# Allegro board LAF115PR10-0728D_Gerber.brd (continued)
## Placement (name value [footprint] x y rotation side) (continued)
EC2901  1000P_0402_50V7K  [C_0402]  31.42 64.37 0 top
EC2902  .1U_0402_16V7K  [C_0402]  220.77 66.04 90 top
EC3001  .1U_0402_16V7K  [C_0402]  85.95 47.96 90 top
EC3002  .1U_0402_16V7K  [C_0402]  50.48 41.56 90 top
EC3003  0.1U_0402_25V6  [C_0402]  28.91 23.76 0 top
ED2901  -  [L03ESDL5V0CC3-2_SOT23-3]  32.58 60.6 0 top
EU2601  -  [L05ESDL5V0NA-4_SLP2510P8-10-9]  19.55 56.9 270 top
EU2602  -  [AZC199-02SPR7G_SOT23-3]  30.43 55.79 90 top
EU2603  -  [L05ESDL5V0NA-4_SLP2510P8-10-9]  19.34 30.9 315 top
EU2604  -  [AZC199-02SPR7G_SOT23-3]  28.99 39.56 270 bottom
EU2701  -  [AZC199-02SPR7G_SOT23-3]  219.81 35.37 0 bottom
EU3101  -  [L05ESDL5V0NA-4_SLP2510P8-10-9]  189.37 36.47 0 top
EU4001  -  [L05ESDL5V0NA-4_SLP2510P8-10-9]  19.95 130.36 270 bottom
EU4002  -  [L05ESDL5V0NA-4_SLP2510P8-10-9]  26.88 123.22 180 bottom
EU4011  -  [L30ESD24VC3-2_SOT23-3]  13.65 131 180 top
EU4012  -  [AZC199-02SPR7G_SOT23-3]  52.1 89.7 90 top
F1  1.5A_24V_SMD1812P150TF-24  [F_SMD1812P150TF-24]  209.38 52.42 90 bottom
F2  1.1A_24V_SMD1812P110TF-24  [F_SMD1812P110TF-24]  215.37 37.63 180 top
F3  0.5A_13.2V_MF-NSMF050-2  [F_MF-NSMF050-2]  48.24 41.06 180 top
FD1  FIDUCAL  [FIDUCIAL_C40M80]  13.81 113.14 0 top
FD2  FIDUCAL  [FIDUCIAL_C40M80]  223.33 26.42 0 top
FD3  FIDUCAL  [FIDUCIAL_C40M80]  53.5 138.49 180 bottom
FD4  FIDUCAL  [FIDUCIAL_C40M80]  225.4 55.81 180 bottom
FI1  1.5A_6V_1206L150PR~D  [F_1206L150PR]  16.59 99.9 90 top
H1  HOLEA  [H_3P0]  6.85 130.5 0 top
H3  HOLEA  [H_5P0]  169.05 109.5 0 top
H4  HOLEA  [H_3P0]  7.9 85.8 0 top
H5  HOLEA  [H_3P0-G]  8 41.2 0 top
H6  HOLEA  [H_3P0-G]  207.45 63.85 0 top
H7  HOLEA  [H_3P0]  141.55 27.1 0 top
H8  HOLEA  [H_3P3-G]  6.9 112.6 0 top
H9  HOLEA  [H_3P5]  142.95 117.18 180 bottom
H10  HOLEA  [H_3P5]  101.31 130.35 180 bottom
H11  HOLEA  [H_3P2]  126.01 153.05 180 bottom
H12  HOLEA  [H_3P2-G]  45.5 129.9 0 top
H13  HOLEA  [H_3P0X4P0]  213.85 65.5 90 top
H14  HOLEA  [H_5P6N]  19.1 111.3 90 top
HCPU1  HOLEA  [H_4P0X3P7]  113.08 100.81 0 top
HCPU2  HOLEA  [H_3P7]  137.38 100.78 0 top
HCPU3  HOLEA  [H_4P0]  113.08 39.78 0 top
HCPU4  HOLEA  [H_3P7X4P0]  137.38 39.81 0 top
JCCG4  CVILU_CH31052VA00-NH  [DC021611210]  42.83 115.5 90 bottom
JCMOS1  SHORT PADS~D  [SHORTPADS]  96.9 77 90 bottom
JDEG1  JXT_FP241AH-010GAAM  [JXT_FP241AH-010GAAM_10P]  45.24 88.83 180 bottom
JDIMM1  DEREN_40-42271-26001RHF  [LOTES_ADDR0206-P001A02_260P]  79.15 109.99 90 bottom
JDIMM2  DEREN_40-42261-26001RHF  [LOTES_ADDR0205-P001A02_260P]  66.45 109.99 270 bottom
JEDP1  ACES_51540-04001-P01  [ACES_51540-04001-P01_40P]  212.37 60.45 270 bottom
JESPI1  JXT_FP241AH-010GAAM  [JXT_FP241AH-010GAAM_10P]  44.69 94.37 90 bottom
JFAN1  ACES_50224-00401-001  [ACES_50224-00401-001_4P]  179.96 68.62 45 bottom
JFP  ACES_51522-00601-001  [ACES_51522-00601-001_6P]  220.02 30.77 180 bottom
JFP1  ACES_51522-00801-001  [ACES_51522-00801-001_8P]  221.02 30.77 180 bottom
JHDD  ACES_50406-02071-001  [ACES_50406-02071-001_20P]  180.7 35.58 0 bottom
JHDD1  ACES_51625-01201-001  [ACES_51625-01201-001_12P]  190.2 35.58 180 bottom
JHDMI1  CONCR_099AKAC19NBLCNF  [ACON_HMRF6-AK120C_19P-T]  11.05 92.35 90 bottom
JHP1  YUQIU_PJ753-F07J1BE-B  [YUQIU_PJ753-F07J1BE-B_7P-T]  12.65 7.9 90 bottom
JIOB1  ACES_51524-0160N-001  [ACES_51524-0160N-001_16P]  213.24 36.75 180 bottom
JKB1  HEFEN_AFB02-S30F1A-HF  [HEFEN_AFB02-S30F1A-HF_30P-T]  59.75 34.05 180 bottom
JKBBL1  ACES_51575-00401-001  [ACES_51575-00401-001_4P]  95.05 34.52 180 bottom
JLAN1  SANTA_130460-N  [SINGA_2RJ3076-078211F_8P-T]  12.95 77.72 90 bottom
JODD1  ACES_50673-0120N-P01  [ACES_50673-0120N-P01_12P]  185.2 64.3 180 bottom
JP1  -  [JUMP_43X79]  156.34 37.08 90 top
JP2  PAD-OPEN1X1M  [JUMP_43X39]  160.85 36.57 270 top
JP5  -  [JUMP_43X79]  178.75 39.58 270 top
JP6  -  [JUMP_43X79]  195.64 63.85 0 top
JP7  -  [JUMP_43X79]  119.83 114.12 90 bottom
JP8  -  [JUMP_43X79]  121.01 109.08 180 bottom
JP9  -  [JUMP_43X79]  131.23 114.91 180 bottom
JP10  -  [JUMP_43X79]  28.29 31.26 90 top
JP11  2MM  [JUMP_43X39]  15.57 85.34 180 top
JP13  -  [JUMP_43X79]  20.29 56.66 90 bottom
JP14  -  [JUMP_43X39]  39.57 127.12 0 top
JPWR1  JXT_FP226H-004S1AM  [JXT_FP226H-004S1AM_4P]  221.24 63.38 0 bottom
JPWR2  JXT_FP226H-006S1BM  [JXT_FP226H-006S1BM_6P]  219.2 63.38 0 bottom
JSPK1  ACES_50224-00401-001  [ACES_50224-00401-001_4P]  16.42 5.88 180 bottom
JSSD1  LCN_DAN05-67306-0103  [LCN_DAN05-67306-0103_75P]  39.38 34.03 180 bottom
JTP1  ACES_51524-0080N-001  [ACES_51524-0080N-001_8P]  125.05 30.5 180 bottom
JUSB1  ACON_TARAN-9R1391  [ACON_TARAN-9R1391_9P]  15.88 56.65 90 bottom
JUSB2  ACON_TARAN-9R1391  [ACON_TARAN-9R1391_9P]  15.88 32.75 90 bottom
JUSBC1  JAE_DX07S024JJ2R1300~D  [JAE_DX07S024JJ2R1300_24P]  7.35 123.82 270 top
JVGA  ACES_51625-01601-001  [ACES_51625-01601-001_16P-T]  217.65 38.75 90 top
JWLAN1  LCN_DAN05-67306-0100  [LCN_DAN05-67306-0100_75P]  79.02 120.65 90 bottom
JWWAN  ACES_51540-03041-001  [ACES_51540-03041-P01_30P-T]  217.23 47.74 90 top
L1  BLM15BD601SN1D_2P  [MURAT_BLM15BD601SN1D_2P]  126.49 59.34 270 top
L2  BLM15BD601SN1D_2P  [MURAT_BLM15BD601SN1D_2P]  120.15 61.43 0 top
L3  MCM1012B900F06BP_4P  [INPAQ_MCM1012B900F06BP_4P]  215.42 43.99 180 top
L4  MCM1012B900F06BP_4P  [INPAQ_MCM1012B900F06BP_4P-NPM]  209.07 40.11 180 top
L5  BLM15PX221SN1D_2P  [MURAT_BLM15PX221SN1D_2P]  32.6 11.25 180 top
L6  BLM15BD221SN1D_2P  [MURAT_BLM15BB221SN1D_2P]  214.68 47.71 0 top
LED1  LTW-295DSKS-5A_YEL-WHITE~D  [LED_LTW-295DSKS-5A_4P]  3.25 133.05 270 bottom
LI1  HCM1012GH900BP_4P  [INPAQ_HCM1012GH900BP_4P-NPM]  15.9 94.4 0 top
LI2  HCM1012GH900BP_4P  [INPAQ_HCM1012GH900BP_4P-NPM]  15.9 96.43 0 top
LI3  HCM1012GH900BP_4P  [INPAQ_HCM1012GH900BP_4P-NPM]  15.9 90.46 0 top
LI4  HCM1012GH900BP_4P  [INPAQ_HCM1012GH900BP_4P-NPM]  15.9 92.43 0 top
LT1  BLM15PX600SN1D_2P  [MURAT_BLM15PX600SN1D_2P]  15.29 127.93 90 bottom
LT2  MCM1012B900F06BP_4P  [INPAQ_MCM1012B900F06BP_4P]  32.27 130.41 0 bottom
LT3  MCM1012B900F06BP_4P  [INPAQ_MCM1012B900F06BP_4P-NPM]  24.71 131.74 0 bottom
LT4  MCM1012B900F06BP_4P  [INPAQ_MCM1012B900F06BP_4P-NPM]  28.19 124.65 90 bottom
LU1  MCM1012B900F06BP_4P  [INPAQ_MCM1012B900F06BP_4P]  33.45 53.04 270 top
LU2  HCM1012GH900BP_4P  [INPAQ_HCM1012GH900BP_4P-NPM]  21.79 58.9 0 top
LU3  HCM1012GH900BP_4P  [INPAQ_HCM1012GH900BP_4P-NPM]  21.79 57.06 0 top
LU4  MCM1012B900F06BP_4P  [INPAQ_MCM1012B900F06BP_4P]  31.06 39.54 0 bottom
LU5  HCM1012GH900BP_4P  [INPAQ_HCM1012GH900BP_4P-NPM]  17.86 34.2 90 top
LU6  HCM1012GH900BP_4P  [INPAQ_HCM1012GH900BP_4P-NPM]  19.88 34.2 90 top
LU8  MCM1012B900F06BP_4P  [INPAQ_MCM1012B900F06BP_4P]  210.76 34.08 270 top
LU9  MCM1012B900F06BP_4P  [INPAQ_MCM1012B900F06BP_4P]  207.64 34.13 270 top
LV2  BLM15BD121SN1D_0402  [R_0402]  110.11 134.45 270 top
LV3  BLM15BD121SN1D_0402  [R_0402]  109.78 136 59.6 top
LV4  BLM15BD121SN1D_0402  [R_0402]  108.77 134.18 90 bottom
LV6  BLM15BD221SN1D_2P  [MURAT_BLM15BB221SN1D_2P]  126.46 123.65 90 top
LV7  BLM15BD121SN1D_0402  [R_0402]  131.22 119.15 0 top
LV8  BLM15BD121SN1D_0402  [R_0402]  133.82 119.54 180 top
NOREF  -  []  92.84 -15.43 0 top
NOREF#2  -  []  113.08 100.81 0 top
NOREF#3  -  []  126.01 153.05 0 top
NOREF#4  -  []  207.45 63.85 0 top
NOREF#5  -  []  91.49 102.94 0 top
NOREF#6  -  []  8 41.2 0 top
NOREF#7  -  []  100.28 116.73 270 top
NOREF#8  -  []  63.97 37.47 0 top
NOREF#9  -  []  101.31 130.35 0 top
NOREF#10  -  []  141.55 27.1 0 top
NOREF#11  -  []  78.39 52.24 0 top
NOREF#12  -  []  45.5 129.9 0 top
NOREF#13  -  []  137.38 39.81 0 top
NOREF#14  -  []  88.71 57.96 0 top
NOREF#15  -  []  137.38 100.81 0 top
NOREF#16  -  []  6.85 130.5 0 top
NOREF#17  -  []  6.9 112.6 0 top
NOREF#18  -  []  142.95 117.18 0 top
NOREF#19  -  []  113.08 39.81 0 top
NOREF#20  -  []  87.68 82.91 0 top
NOREF#21  -  []  213.85 65.5 0 top
NOREF#22  -  []  134.03 102.94 180 bottom
NOREF#23  -  []  145.35 69.81 180 bottom
NOREF#24  -  []  133.97 94.71 180 bottom
NOREF#25  -  []  95.92 50.35 180 bottom
PBATT1  -  [ACES_50458-01001-P01_10P-T]  173.01 40 180 bottom
PC1  1000P_0402_50V7K  [C_0402]  88.06 140.21 270 top
PC2  2200P_0402_25V7K  [C_0402]  87.12 140.21 270 top
PC3  1000P_0402_50V7K  [C_0402]  82.7 147.94 90 top
PC4  2200P_0402_25V7K  [C_0402]  84.6 147.94 90 top
PC5  0.022U_0603_50V7K  [C_0603]  92.01 145.13 270 top
PC6  0.022U_0603_50V7K  [C_0603]  101.47 147.61 180 top
PC7  0.1U_0402_50V7K  [C_0402]  89.92 149.3 270 bottom
PC8  1000P_0603_50V7K  [C_0603]  85.68 147.77 90 top
PC9  2.2U_0402_10V6M  [C_0402]  81.77 147.94 90 top
PC10  0.1U_0402_50V7K  [C_0402]  95.65 144.41 0 bottom
PC11  0.01U_0402_25V7K  [C_0402]  146.53 34.34 270 bottom
PC12  1000P_0402_50V7K  [C_0402]  150.52 40.1 90 bottom
PC13  .1U_0402_16V7K  [C_0402]  169.25 28.94 90 top
PC14  .1U_0402_16V7K  [C_0402]  177.92 30.49 270 top
PC15  10P_0402_25V8J  [C_0402]  89.02 140.21 270 top
PC16  82P_0402_50V8J  [C_0402]  83.65 147.94 90 top
PC17  82P_0402_50V8J  [C_0402]  151.42 40.11 90 bottom
PC18  0.1U_0402_25V7K  [C_0402]  149.6 40.11 90 bottom
PC21  0.1U_0402_10V7K  [C_0402]  92.72 147.52 180 top
PC22  0.1U_0402_10V7K  [C_0402]  86.97 148.26 90 top
PC23  0.1U_0402_10V7K  [C_0402]  88.11 142.68 90 bottom
PC301  1000P_0402_25V8J  [C_0402]  14.03 38.94 180 bottom
PC302  2200P_0402_50V7K  [C_0402]  14.04 41.66 180 bottom
PC303  4.7U_0805_25V6K  [C_0805]  18.04 41.77 90 top
PC304  4.7U_0805_25V6K  [C_0805]  16.44 40.97 90 bottom
PC305  0.1U_0402_25V6  [C_0402]  14.04 40.77 180 bottom
PC306  1000P_0402_25V8J  [C_0402]  14.03 39.87 180 bottom
PC307  0.1U_0402_10V7K  [C_0402]  23.35 40.42 90 bottom
PC308  4.7U_0402_6.3V6M  [C_0402]  21.38 43.85 270 top
PC309  680P_0603_50V7K  [C_0603]  22.65 44.38 270 top
PC310  22U_0805_6.3V6M  [C_0805]  24.61 52.77 180 bottom
PC311  22U_0805_6.3V6M  [C_0805]  27.5 52.84 0 bottom
PC312  22U_0805_6.3V6M  [C_0805]  24.53 52.74 180 top
PC313  22U_0805_6.3V6M  [C_0805]  27.5 52.84 0 top
PC314  22U_0805_6.3V6M  [C_0805]  24.63 54.53 180 bottom
PC315  1000P_0402_25V8J  [C_0402]  21.51 46.11 90 bottom
PC316  82P_0402_50V8J  [C_0402]  15.06 40.79 90 bottom
PC501  1000P_0402_25V8J  [C_0402]  25.7 101.82 180 bottom
PC502  2200P_0402_50V7K  [C_0402]  25.7 102.71 180 bottom
PC503  10U_0805_25V6K  [C_0805]  28.93 99.08 270 top
PC504  10U_0805_25V6K  [C_0805]  28.96 99.08 270 bottom
PC505  0.1U_0402_25V6  [C_0402]  25.7 100.94 180 bottom
PC506  1000P_0402_25V8J  [C_0402]  25.7 100.05 180 bottom
PC507  0.1U_0402_10V7K  [C_0402]  23.61 102.55 90 bottom
PC508  4.7U_0402_6.3V6M  [C_0402]  23.95 96.87 90 top
PC509  680P_0603_50V7K  [C_0603]  19.1 100.93 90 top
PC510  22U_0805_6.3V6M  [C_0805]  24.13 106.74 270 top
PC511  22U_0805_6.3V6M  [C_0805]  25.84 106.73 270 top
PC512  22U_0805_6.3V6M  [C_0805]  27.59 106.73 270 bottom
PC513  22U_0805_6.3V6M  [C_0805]  25.84 106.73 270 bottom
PC514  22U_0805_6.3V6M  [C_0805]  24.13 106.73 270 bottom
PC515  4.7U_0402_6.3V6M  [C_0402]  24.63 95.79 0 top
PC516  4.7U_0402_6.3V6M  [C_0402]  26.86 92.34 180 bottom
PC517  1000P_0402_25V8J  [C_0402]  25.05 93.23 270 bottom
PC518  82P_0402_50V8J  [C_0402]  25.7 103.6 180 bottom
PC519  22U_0805_6.3V6M  [C_0805]  23.82 103.17 0 top
PC1801  22U_0603_6.3V6M  [C_0603]  170.35 42.1 180 bottom
PC1802  22U_0603_6.3V6M  [C_0603]  157.51 43.4 270 top
PC1803  22U_0603_6.3V6M  [C_0603]  157.51 45.43 90 bottom
PC1804  22U_0603_6.3V6M  [C_0603]  157.51 43.39 270 bottom
PC1805  0.1U_0402_10V7K  [C_0402]  167.66 46.57 0 bottom
PC1806  680P_0402_50V7K  [C_0402]  166.11 43.58 0 top
PC1807  22P_0402_50V8J  [C_0402]  170.21 47.44 270 bottom
PC1808  82P_0402_50V8J  [C_0402]  171.94 45.04 90 bottom
PC1809  0.1U_0402_25V6  [C_0402]  173.84 45.03 90 bottom
PC1810  2200P_0402_50V7K  [C_0402]  172.91 45.04 90 bottom
PC2501  10U_0805_10V6K  [C_0805]  73.62 113.39 90 top
PC2502  10U_0805_10V6K  [C_0805]  64.3 113.5 90 top
PC2503  0.1U_0402_10V6K  [C_0402]  73.19 111.01 270 top
PC2504  1U_0402_6.3V6K  [C_0402]  72.3 115.43 90 top
PC2505  0.01U_0402_25V7K  [C_0402]  64.74 112.42 270 top
PCA01  10U_0805_25V6K  [C_0805]  161.95 60.03 270 top
PCA02  10U_0805_25V6K  [C_0805]  161.95 60.03 270 bottom
PCA03  0.1U_0402_25V6  [C_0402]  162.72 62.72 90 bottom
PCA04  2200P_0402_50V7K  [C_0402]  159.86 62.72 90 bottom
PCA05  1000P_0402_50V7K  [C_0402]  160.82 62.72 90 bottom
PCA06  1000P_0402_50V7K  [C_0402]  161.77 62.72 90 bottom
PCA07  0.22U_0603_16V7K  [C_0603]  163.89 59.7 270 top
PCA08  2.2U_0603_16V6K  [C_0603]  166.37 58.12 180 top
PCA09  680P_0603_50V7K  [C_0603]  157.43 58.93 0 top
PCA101  22U_0603_6.3V6M  [C_0603]  148.99 61.94 270 top
PCA102  22U_0603_6.3V6M  [C_0603]  129.3 64.27 90 top
PCA103  22U_0603_6.3V6M  [C_0603]  128.09 64.27 90 top
PCA104  22U_0603_6.3V6M  [C_0603]  126.89 64.27 90 top
PCA105  22U_0603_6.3V6M  [C_0603]  125.68 64.27 90 top
PCA106  22U_0603_6.3V6M  [C_0603]  124.47 64.27 90 top
PCA107  22U_0603_6.3V6M  [C_0603]  130.51 64.27 90 top
PCA108  22U_0603_6.3V6M  [C_0603]  123.24 64.26 90 top
PCA109  22U_0603_6.3V6M  [C_0603]  149 61.95 270 bottom
PCA110  1U_0201_6.3V6M  [C_0201]  127.04 63.41 270 top
PCA111  1U_0201_6.3V6M  [C_0201]  131.43 64.18 270 top
PCA112  1U_0201_6.3V6M  [C_0201]  132.84 65.4 0 top
PCA113  1U_0201_6.3V6M  [C_0201]  122.3 64.66 270 top
PCA114  1U_0201_6.3V6M  [C_0201]  122.3 65.28 90 top
PCA115  1U_0201_6.3V6M  [C_0201]  121.73 64.02 270 top
PCA116  1U_0201_6.3V6M  [C_0201]  131.45 65.31 90 top
PCB01  0.1U_0402_25V6  [C_0402]  200.99 58.27 0 bottom
PCB02  2200P_0402_50V7K  [C_0402]  200.99 57.34 0 bottom
PCB03  22U_0805_25V6M  [C_0805]  200.6 55.99 0 top
PCB04  22U_0805_25V6M  [C_0805]  200.6 54.27 0 top
PCB05  22U_0805_25V6M  [C_0805]  200.6 55.99 0 bottom
PCB06  22U_0805_25V6M  [C_0805]  200.6 54.27 0 bottom
PCB07  33U_D2_25VM_R40M  [C_EEFCX1E330R]  192.24 58.17 180 bottom
PCB08  33U_25V_M  [C_6P3X4P5-NPM]  192.65 58.26 0 bottom
PCB10  10U_0805_25V6K~D  [C_0805]  181.64 45.97 90 bottom
PCB11  10U_0805_25V6K~D  [C_0805]  186.28 40.03 270 bottom
PCB12  10U_0805_25V6K~D  [C_0805]  181.64 45.97 90 top
PCB13  10U_0805_25V6K~D  [C_0805]  189.83 40.04 270 bottom
PCB14  10U_0805_25V6K~D  [C_0805]  188.05 40.03 270 bottom
PCB15  10U_0805_25V6K~D  [C_0805]  186.38 40.02 270 top
PCB16  10U_0805_25V6K~D  [C_0805]  189.94 40.03 270 top
PCB17  10U_0805_25V6K~D  [C_0805]  188.16 40.02 270 top
PCB18  4.7U_0402_6.3V6M  [C_0402]  201.04 48.07 270 bottom
PCB19  1U_0402_25V6K  [C_0402]  200.83 48.78 180 top
PCB20  1U_0402_25V6K  [C_0402]  200.83 47.84 180 top
PCB21  0.1U_0402_25V6  [C_0402]  180.35 45.19 180 bottom
PCB22  2200P_0402_50V7K  [C_0402]  180.37 46.13 180 bottom
PCB23  2200P_0402_50V7K  [C_0402]  184.91 40.07 270 bottom
PCB24  1000P_0402_50V7K  [C_0402]  180.37 47.05 180 bottom
PCB25  0.22U_0603_25V7K  [C_0603]  199.57 44.9 270 bottom
PCB26  0.1U_0402_25V6  [C_0402]  200.58 50.97 180 bottom
PCB27  1U_0603_25V6  [C_0603]  203.34 49.47 270 top
PCB28  1U_0402_6.3V6K  [C_0402]  203.82 51.62 90 bottom
PCB29  1U_0402_6.3V6K  [C_0402]  202.32 45.64 0 top
PCB30  0.22U_0603_25V7K  [C_0603]  203.26 41.17 270 bottom
PCB31  10U_0805_25V6K~D  [C_0805]  177.94 45.01 90 top
PCB32  10U_0805_25V6K~D  [C_0805]  177.94 44.99 90 bottom
PCB33  4700P_0402_25V7K  [C_0402]  146.6 31.67 90 bottom
PCB34  10P_0402_50V8J  [C_0402]  206.74 45.44 180 top
PCB35  0.1U_0402_25V6  [C_0402]  203.94 41.26 270 top
PCB36  680P_0603_50V7K  [C_0603]  187.28 51.51 270 top
PCB37  680P_0603_50V7K  [C_0603]  190.38 46.2 180 top
PCB38  1U_0402_25V6K  [C_0402]  204.86 41.26 270 top
PCB39  560P_0402_50V7K  [C_0402]  208.19 46.16 0 bottom
PCB40  0.1U_0402_25V6  [C_0402]  209.96 43.5 0 bottom
PCB41  1U_0402_25V6K  [C_0402]  205.22 41.2 0 bottom
PCB42  0.01UF_0402_25V7K  [C_0402]  209.98 47.05 270 bottom
PCB43  0.22U_0402_25V6K  [C_0402]  205.77 41.25 270 top
PCB44  0.1U_0402_10V7K  [C_0402]  168.05 33.84 90 top
PCB45  0.1U_0402_25V6  [C_0402]  208.24 42.82 0 top
PCB46  82P_0402_50V8J  [C_0402]  180.3 44.28 180 bottom
PCB47  82P_0402_50V8J  [C_0402]  191.28 61.05 180 bottom
PCC01  22U_0603_6.3V6M  [C_0603]  122.99 76.84 0 top
PCC02  22U_0603_6.3V6M  [C_0603]  120.65 77.25 0 top
PCC03  22U_0603_6.3V6M  [C_0603]  130.56 75.62 180 top
PCC04  22U_0603_6.3V6M  [C_0603]  130.56 76.83 180 top
PCG01  10U_0805_25V6K  [C_0805]  163.55 92.86 270 bottom
PCG02  10U_0805_25V6K  [C_0805]  163.55 92.85 270 top
PCG03  10U_0805_25V6K  [C_0805]  165.26 92.86 270 bottom
PCG04  10U_0805_25V6K  [C_0805]  165.26 92.86 270 top
PCG05  0.1U_0402_25V6  [C_0402]  168.8 90.28 180 bottom
PCG06  2200P_0402_50V7K  [C_0402]  168.8 91.16 180 bottom
PCG07  1000P_0402_50V7K  [C_0402]  167.58 93.02 270 bottom
PCG08  1000P_0402_50V7K  [C_0402]  166.63 93.02 270 bottom
PCG09  0.22U_0603_25V7K  [C_0603]  161.29 97.9 270 bottom
PCG10  1U_0402_16V6K  [C_0402]  158.99 96.78 90 bottom
PCG11  1U_0402_16V6K  [C_0402]  157.13 93.98 270 top
PCG12  680P_0603_50V8J  [C_0603]  156.12 90.76 90 top
PCG13  33U_D2_25VM_R40M  [C_EEFCX1E330R]  165.86 95.39 270 bottom
PCG101  22U_0603_6.3V6M  [C_0603]  127.89 83.42 270 top
PCG102  22U_0603_6.3V6M  [C_0603]  126.68 83.42 270 top
PCG103  22U_0603_6.3V6M  [C_0603]  128.45 79.75 270 top
PCG104  22U_0603_6.3V6M  [C_0603]  124.27 83.42 270 top
PCG105  22U_0603_6.3V6M  [C_0603]  126.04 79.75 270 top
PCG106  22U_0603_6.3V6M  [C_0603]  123.62 79.75 270 top
PCG107  22U_0603_6.3V6M  [C_0603]  118.91 90.99 90 top
PCG108  22U_0603_6.3V6M  [C_0603]  124.02 80.85 180 top
PCG109  22U_0603_6.3V6M  [C_0603]  150.05 105.25 0 top
PCG110  22U_0603_6.3V6M  [C_0603]  125.48 83.42 270 top
PCG111  22U_0603_6.3V6M  [C_0603]  122.4 79.74 270 top
PCG112  22U_0603_6.3V6M  [C_0603]  130.43 80.93 180 top
PCG113  22U_0603_6.3V6M  [C_0603]  131.48 89.72 90 top
PCG114  22U_0603_6.3V6M  [C_0603]  124.83 79.75 270 top
PCG115  22U_0603_6.3V6M  [C_0603]  123.06 83.42 270 top
PCG116  22U_0603_6.3V6M  [C_0603]  127.24 79.75 270 top
PCG117  22U_0603_6.3V6M  [C_0603]  121.76 90.99 90 top
PCG118  22U_0603_6.3V6M  [C_0603]  130.3 83.42 270 top
PCG119  22U_0603_6.3V6M  [C_0603]  150.05 105.25 0 bottom
PCG120  22U_0603_6.3V6M  [C_0603]  144.59 105.48 180 top
PCG121  22U_0603_6.3V6M  [C_0603]  146.29 105.35 90 bottom
PCG122  22U_0603_6.3V6M  [C_0603]  147.52 105.36 90 bottom
PCG123  22U_0603_6.3V6M  [C_0603]  141.8 104.59 135 bottom
PCG124  22U_0603_6.3V6M  [C_0603]  148.73 105.37 90 top
PCG125  22U_0603_6.3V6M  [C_0603]  150.05 106.46 0 top
PCG126  22U_0603_6.3V6M  [C_0603]  126.46 80.84 180 top
PCG127  22U_0603_6.3V6M  [C_0603]  147.94 99.08 0 top
PCG128  22U_0603_6.3V6M  [C_0603]  146.29 105.35 90 top
PCG129  22U_0603_6.3V6M  [C_0603]  148.73 105.37 90 bottom
PCG130  22U_0603_6.3V6M  [C_0603]  129.1 83.42 270 top
PCG131  22U_0603_6.3V6M  [C_0603]  147.51 105.37 90 top
PCG132  22U_0603_6.3V6M  [C_0603]  144.59 105.48 180 bottom
PCG133  22U_0603_6.3V6M  [C_0603]  150.05 106.46 0 bottom
PCG134  0.47U_0201_6.3V6K  [C_0201]  125.44 85.08 180 top
PCG135  0.47U_0201_6.3V6K  [C_0201]  129.21 90.15 0 top
PCG136  0.47U_0201_6.3V6K  [C_0201]  132.06 81.02 0 top
PCG137  0.47U_0201_6.3V6K  [C_0201]  124.86 90.29 180 top
PCG138  1U_0201_6.3V6M  [C_0201]  128.13 81.14 180 top
PCG139  1U_0201_6.3V6M  [C_0201]  122.09 83.69 180 top
PCG140  1U_0201_6.3V6M  [C_0201]  131.76 80.13 0 top
PCG141  1U_0201_6.3V6M  [C_0201]  132.48 82.79 0 top
PCG142  1U_0201_6.3V6M  [C_0201]  131.2 83.03 270 top
PCG143  1U_0201_6.3V6M  [C_0201]  128.13 80.57 180 top
PCG144  1U_0201_6.3V6M  [C_0201]  123.4 84.2 180 top
PCG145  1U_0201_6.3V6M  [C_0201]  122.09 83.12 180 top
PCG146  1U_0201_6.3V6M  [C_0201]  131.23 84.03 90 top
PCG171  220U 2V Y D2  [C_D2]  149.49 102.26 0 bottom
PCG172  220U 2V Y D2  [C_D2]  144.97 102.81 270 bottom
PCH01  0.1U_0402_25V6  [C_0402]  161.01 55.04 90 top
PCH02  2200P_0402_50V7K  [C_0402]  161.01 55.04 90 bottom
PCH03  10U_0805_25V6K~D  [C_0805]  162.41 54.58 90 bottom
PCH04  10U_0805_25V6K~D  [C_0805]  162.41 54.58 90 top
PCH05  22U_0603_6.3V6M  [C_0603]  149.32 48.26 270 bottom
PCH06  22U_0603_6.3V6M  [C_0603]  150.58 48.27 270 top
PCH07  22U_0603_6.3V6M  [C_0603]  150.59 48.26 270 bottom
PCH08  22U_0603_6.3V6M  [C_0603]  149.31 48.27 270 top
PCH09  0.1U_0402_25V6  [C_0402]  164.87 53.67 0 top
PCH10  1U_0402_10V6K  [C_0402]  164.91 51.76 0 bottom
PCH11  1U_0402_10V6K  [C_0402]  164.93 50.29 0 top
PCH12  0.1U_0402_10V6K  [C_0402]  161.12 50.49 270 top
PCH13  680P_0603_50V7K  [C_0603]  158.14 49.01 0 top
PCH14  330P_0402_50V7K  [C_0402]  166.71 50.97 90 top
PCH15  1000P_0402_50V7K  [C_0402]  160.05 55.04 90 bottom
PCH16  1000P_0402_50V7K  [C_0402]  160.05 55.04 90 top
PCH17  82P_0402_50V8J  [C_0402]  163.76 55.57 90 bottom
PCI01  10U_0805_25V6K  [C_0805]  166.3 79.93 180 top
PCI02  10U_0805_25V6K  [C_0805]  167.83 68.82 90 bottom
PCI03  10U_0805_25V6K  [C_0805]  167.76 67.43 270 bottom
PCI04  10U_0805_25V6K  [C_0805]  166.31 81.77 180 top
PCI05  1000P_0402_50V7K  [C_0402]  170.03 70.92 180 bottom
PCI06  0.1U_0402_25V6  [C_0402]  170.03 71.81 180 bottom
PCI07  2200P_0402_50V7K  [C_0402]  170.02 72.71 180 bottom
PCI08  1000P_0402_50V7K  [C_0402]  167.38 71.53 0 bottom
PCI09  0.22U_0603_25V7K  [C_0603]  165.76 71.63 270 top
PCI10  1U_0402_16V6K  [C_0402]  162.53 70.19 0 top
PCI11  1U_0402_16V6K  [C_0402]  161.38 68.3 270 top
PCI12  680P_0603_50V8J  [C_0603]  159.63 66.32 90 top
PCI13  33U_D2_25VM_R40M  [C_EEFCX1E330R]  167.59 75.51 0 bottom
PCI14  33U_25V_M  [C_6P3X4P5-NPM]  167.37 75.51 180 bottom
PCI21  0.1U_0402_25V6  [C_0402]  168.26 85.39 0 bottom
PCI22  2200P_0402_50V7K  [C_0402]  168.26 86.34 0 bottom
PCI23  10U_0805_25V6K  [C_0805]  169.56 66.53 270 top
PCI24  10U_0805_25V6K  [C_0805]  166.3 81.77 180 bottom
PCI25  10U_0805_25V6K  [C_0805]  167.76 67.42 270 top
PCI26  10U_0805_25V6K  [C_0805]  166.3 79.92 180 bottom
PCI27  1000P_0402_50V7K  [C_0402]  168.26 83.54 0 bottom
PCI28  1000P_0402_50V7K  [C_0402]  168.26 84.43 0 bottom
PCI29  0.22U_0603_25V7K  [C_0603]  168.5 83.12 90 top
PCI30  1U_0402_16V6K  [C_0402]  168.23 87.27 0 bottom
PCI31  1U_0402_16V6K  [C_0402]  164.97 88.12 180 top
PCI32  680P_0603_50V8J  [C_0603]  161.42 88.24 0 top
PCI101  22U_0603_6.3V6M  [C_0603]  125.58 72.58 270 top
PCI102  22U_0603_6.3V6M  [C_0603]  127.93 74.98 270 top
PCI103  22U_0603_6.3V6M  [C_0603]  126.72 74.98 270 top
PCI104  22U_0603_6.3V6M  [C_0603]  125.52 74.98 270 top
PCI105  22U_0603_6.3V6M  [C_0603]  124.37 72.58 270 top
PCI106  22U_0603_6.3V6M  [C_0603]  157.15 77.66 0 bottom
PCI107  22U_0603_6.3V6M  [C_0603]  157.15 75.22 0 bottom
PCI108  22U_0603_6.3V6M  [C_0603]  129.25 68.83 270 top
PCI109  22U_0603_6.3V6M  [C_0603]  128.04 68.83 270 top
PCI110  22U_0603_6.3V6M  [C_0603]  126.84 68.83 270 top
PCI111  22U_0603_6.3V6M  [C_0603]  123.18 68.8 270 top
PCI112  22U_0603_6.3V6M  [C_0603]  157.15 76.44 0 bottom
PCI113  22U_0603_6.3V6M  [C_0603]  124.31 74.98 270 top
PCI114  22U_0603_6.3V6M  [C_0603]  129.2 72.58 270 top
PCI115  22U_0603_6.3V6M  [C_0603]  127.99 72.58 270 top
PCI116  22U_0603_6.3V6M  [C_0603]  126.79 72.58 270 top
PCI117  22U_0603_6.3V6M  [C_0603]  146.98 79.9 270 top
PCI118  22U_0603_6.3V6M  [C_0603]  146.98 79.9 270 bottom
PCI119  22U_0603_6.3V6M  [C_0603]  157.07 74.04 0 top
PCI120  22U_0603_6.3V6M  [C_0603]  145.75 79.89 270 bottom
PCI121  22U_0603_6.3V6M  [C_0603]  125.49 75.99 90 top
PCI122  22U_0603_6.3V6M  [C_0603]  145.75 79.89 270 top
PCI123  22U_0603_6.3V6M  [C_0603]  157.07 76.45 0 top
PCI124  22U_0603_6.3V6M  [C_0603]  125.63 68.83 270 top
PCI125  22U_0603_6.3V6M  [C_0603]  124.42 68.83 270 top
PCI126  22U_0603_6.3V6M  [C_0603]  157.07 75.24 0 top
PCI127  22U_0603_6.3V6M  [C_0603]  157.07 77.66 0 top
PCI128  22U_0603_6.3V6M  [C_0603]  128 75.97 90 top
PCI129  1U_0201_6.3V6M  [C_0201]  120.44 70.97 180 top
PCI130  1U_0201_6.3V6M  [C_0201]  120.44 71.54 180 top
PCI131  1U_0201_6.3V6M  [C_0201]  132.48 68.64 0 top
PCI132  1U_0201_6.3V6M  [C_0201]  120.44 69.76 180 top
PCI133  1U_0201_6.3V6M  [C_0201]  120.44 69.19 180 top
PCI134  1U_0201_6.3V6M  [C_0201]  122.27 68.68 270 top
PCI135  1U_0201_6.3V6M  [C_0201]  121.07 74.4 135 top
PCI136  1U_0201_6.3V6M  [C_0201]  127.97 69.71 180 top
PCI137  1U_0201_6.3V6M  [C_0201]  124.55 69.69 0 top
PCI138  1U_0201_6.3V6M  [C_0201]  128.75 66.52 0 top
PCI139  1U_0201_6.3V6M  [C_0201]  125.85 66.54 0 top
PCI140  1U_0201_6.3V6M  [C_0201]  127.63 66.53 180 top
PCI141  1U_0201_6.3V6M  [C_0201]  124.72 66.53 180 top
PCI142  1U_0201_6.3V6M  [C_0201]  127.96 70.37 180 top
PCI143  1U_0201_6.3V6M  [C_0201]  126.98 75.99 180 top
PCI144  1U_0201_6.3V6M  [C_0201]  126.98 77.44 180 top
PCI145  1U_0201_6.3V6M  [C_0201]  120.44 68.62 180 top
PCI146  1U_0201_6.3V6M  [C_0201]  130.51 66.52 180 top
PCI147  1U_0201_6.3V6M  [C_0201]  129.45 69.7 180 top
PCI148  1U_0201_6.3V6M  [C_0201]  123.34 69.69 0 top
PCI149  1U_0201_6.3V6M  [C_0201]  126.98 76.72 180 top
PCI150  1U_0201_6.3V6M  [C_0201]  123.33 70.33 0 top
PCI151  1U_0201_6.3V6M  [C_0201]  132.93 66.67 180 top
PCI152  1U_0201_6.3V6M  [C_0201]  130.66 70.37 180 top
PCI153  1U_0201_6.3V6M  [C_0201]  129.45 70.35 180 top
PCI154  1U_0201_6.3V6M  [C_0201]  124.54 70.32 0 top
PCI155  1U_0201_6.3V6M  [C_0201]  125.87 70.36 0 top
PCI156  1U_0201_6.3V6M  [C_0201]  123.99 75.81 0 top
PCI157  1U_0201_6.3V6M  [C_0201]  125.87 69.7 0 top
PCI158  1U_0201_6.3V6M  [C_0201]  130.64 69.69 180 top
PCI159  1U_0201_6.3V6M  [C_0201]  122.94 66.55 0 top
PCI160  1U_0201_6.3V6M  [C_0201]  122.17 70.92 0 top
PCI161  1U_0201_6.3V6M  [C_0201]  122.14 70.34 0 top
PCI162  1U_0201_6.3V6M  [C_0201]  122.15 69.68 0 top
PCI163  1U_0201_6.3V6M  [C_0201]  120.44 70.4 180 top
PCI171  220U 2V Y D2  [C_D2]  145.67 68.62 270 bottom
PCI172  220U 2V Y D2  [C_D2]  150.5 82.07 90 bottom
PCI173  330U_D2_2V_Y  [C_D2]  150.55 70.59 270 bottom
PCM01  0.1U_0402_25V6  [C_0402]  42.9 24.85 270 bottom
PCM02  2200P_0402_50V7K  [C_0402]  41.98 24.85 270 bottom
PCM03  4.7U_0805_25V6K  [C_0805]  42.38 27.45 90 bottom
PCM04  4.7U_0805_25V6K  [C_0805]  42.38 27.45 90 top
PCM05  22U_0603_6.3V6M  [C_0603]  49.81 31.84 90 top
PCM06  22U_0603_6.3V6M  [C_0603]  49.79 31.85 90 bottom
PCM07  22U_0603_6.3V6M  [C_0603]  51.01 31.85 90 bottom
PCM08  22U_0603_6.3V6M  [C_0603]  48.6 31.85 90 bottom
PCM09  22U_0603_6.3V6M  [C_0603]  48.6 31.84 90 top
PCM10  22U_0603_6.3V6M  [C_0603]  51.01 31.84 90 top
PCM11  680P_0402_50V7K  [C_0402]  51.98 27.96 180 top
PCM12  0.1U_0402_10V7K  [C_0402]  40.83 27.48 180 top
PCM13  1U_0603_10V6K  [C_0603]  36.76 25.3 270 top
PCM14  1U_0603_10V6K  [C_0603]  32.95 25.3 270 top
PCM15  0.1U_0402_10V7K  [C_0402]  33.63 29.13 180 top
PCM16  0.1U_0402_10V7K  [C_0402]  33.64 30.06 180 top
PCM17  220P_0402_25V8J  [C_0402]  34.04 32.25 0 top
PCM18  .1U_0402_16V7K  [C_0402]  35.86 32.21 90 top
PCM19  0.033U_0402_16V7K  [C_0402]  36.78 32.19 90 top
PCM20  10U_0603_6.3V6M  [C_0603]  38.11 33.75 90 top
PCM21  10U_0603_6.3V6M  [C_0603]  39.35 32.39 0 top
PCM22  1000P_0402_50V7K  [C_0402]  41.98 24.85 270 top
PCM23  1000P_0402_50V7K  [C_0402]  42.9 24.85 270 top
PCM24  82P_0402_50V8J  [C_0402]  47.47 26.39 270 top
PCS01  0.01U_0402_25V7K~D  [C_0402]  54.96 119.9 180 top
PCS02  100P_0402_50V8J~D  [C_0402]  47.38 116.25 180 top
PCS03  220P_0402_50V8J~D  [C_0402]  50.59 112.24 180 top
PCS04  1200P_0402_50V7K  [C_0402]  48.21 117.97 0 top
PCS05  100P_0402_50V8J  [C_0402]  44.42 136.6 270 top
PCS06  1000P_0402_50V7K  [C_0402]  45.37 136.6 270 top
PCS07  0.1U_0402_25V6  [C_0402]  47.15 136.6 270 top
PCS08  100P_0402_50V8J  [C_0402]  46.26 136.6 270 top
PCS09  0.47U_0603_25V7K  [C_0603]  49.88 137.35 270 top
PCS10  1500P_0402_50V7K  [C_0402]  65.34 138.55 90 top
PCS11  0.1U_0402_10V7K  [C_0402]  58.82 131.76 0 top
PCS12  0.1U_0402_10V7K  [C_0402]  56.45 128.38 90 top
PCS13  0.1U_0402_10V7K  [C_0402]  57.49 124.66 270 top
PCS14  0.1U_0402_10V7K  [C_0402]  56.59 124.66 270 top
PCS15  1000P_0603_50V7K  [C_0603]  77.12 142.64 0 top
PCS16  2.2U_0402_10V6M  [C_0402]  79.5 142.62 0 top
PCS17  0.1U_0402_10V7K  [C_0402]  62.26 126.22 90 top
PCS19  .1U_0402_16V7K  [C_0402]  63.16 124.27 0 top
PCS20  .1U_0402_16V7K  [C_0402]  63.33 117.85 0 top
PCS21  4.7U_0603_25V6K  [C_0603]  59.6 134.13 270 top
PCV01  10U_0805_25V6K~D  [C_0805]  81.78 134.78 270 bottom
PCV02  10U_0805_25V6K~D  [C_0805]  81.78 134.78 270 top
PCV03  4.7U_0805_25V6K  [C_0805]  83.56 134.78 270 top
PCV04  2200P_0402_50V7K  [C_0402]  82.23 139.11 180 bottom
PCV05  0.1U_0402_25V6K  [C_0402]  82.23 138.22 180 bottom
PCV06  2200P_0402_50V7K  [C_0402]  82.23 137.33 180 bottom
PCV07  0.1U_0402_25V6K  [C_0402]  82.23 136.44 180 bottom
PCV08  0.22U_0402_16V7K  [C_0402]  78.39 132.28 270 top
PCV09  680P_0603_50V7K  [C_0603]  92.42 131.71 0 top
PCV10  0.1U_0402_25V6K  [C_0402]  69.57 130.15 90 top
PCV11  1U_0603_10V6K  [C_0603]  80.74 129.73 0 top
PCV12  1U_0603_10V6K  [C_0603]  80.74 131 0 top
PCV13  10U_0805_25V6K~D  [C_0805]  81.69 124.79 90 bottom
PCV14  10U_0805_25V6K~D  [C_0805]  81.69 124.79 90 top
PCV15  4.7U_0805_25V6K  [C_0805]  83.49 124.81 90 bottom
PCV16  2200P_0402_50V7K  [C_0402]  81.82 122.46 180 top
PCV17  0.1U_0402_25V6  [C_0402]  81.82 123.35 180 top
PCV18  2200P_0402_50V7K  [C_0402]  81.82 122.46 180 bottom
PCV19  0.1U_0402_25V6  [C_0402]  81.82 123.35 180 bottom
PCV20  1000P_0402_50V7K  [C_0402]  68.87 128.53 270 top
PCV21  0.22U_0402_16V7K  [C_0402]  79.68 128.33 180 top
PCV22  0.22U_0402_10V6K  [C_0402]  68.87 126.63 270 top
PCV23  0.22U_0402_10V6K  [C_0402]  70.66 125.79 180 top
PCV24  680P_0603_50V7K  [C_0603]  92.45 128.16 0 top
PCV25  1000P_0402_50V7K  [C_0402]  74.66 125.34 180 top
PCV26  180P_0402_50V8J  [C_0402]  73.68 122.8 0 top
PCV27  330P_0402_50V7K  [C_0402]  75.4 124.39 0 top
PCV28  0.033U_0402_16V7K  [C_0402]  70.96 123.49 90 top
PCV29  390P_0402_50V7K  [C_0402]  75.41 121.08 90 top
PCV30  0.15U_0603_16V7K  [C_0603]  69.21 122.99 180 top
PCV31  330P_0402_50V  [C_0402]  72.82 121.03 180 top
PCV32  0.1U_0603_50V7K  [C_0603]  69.21 124.19 180 top
PCV33  820PF_0402_50V7K  [C_0402]  71.78 125.34 0 top
PCV34  0.01U_0402_50V7K  [C_0402]  76.44 125.34 180 top
PCV35  4.7U_0805_25V6K  [C_0805]  83.56 134.78 270 bottom
PCV36  4.7U_0805_25V6K  [C_0805]  83.48 124.82 90 top
PCV171  560U_D2_2VM_R4.5M  [C_D2]  102.9 136.8 90 bottom
PCV172  560U_D2_2VM_R4.5M  [C_D2]  103.38 123.89 270 bottom
PCW01  0.1U_0402_25V6  [C_0402]  138.46 108.22 270 bottom
PCW02  2200P_0402_50V7K  [C_0402]  135.73 108.22 270 bottom
PCW03  10U_0805_25V6K~D  [C_0805]  139.78 109.41 270 top
PCW04  10U_0805_25V6K~D  [C_0805]  139.8 109.37 270 bottom
PCW05  22U_0603_6.3V6M  [C_0603]  154.22 111.67 90 top
PCW06  22U_0603_6.3V6M  [C_0603]  154.31 109.23 270 top
PCW07  22U_0603_6.3V6M  [C_0603]  154.23 111.65 90 bottom
PCW08  22U_0603_6.3V6M  [C_0603]  154.31 109.23 270 bottom
PCW09  0.1U_0402_25V6  [C_0402]  138.44 111.34 90 bottom
PCW10  1U_0402_10V6K  [C_0402]  142.66 111.39 180 bottom
PCW11  1U_0402_10V6K  [C_0402]  144.29 111.43 90 bottom
PCW12  0.1U_0402_10V6K  [C_0402]  147.13 108.23 0 top
PCW13  680P_0603_50V7K  [C_0603]  149.8 111.27 90 top
PCW14  330P_0402_50V7K  [C_0402]  147.06 113.74 90 bottom
PCW15  1000P_0402_50V7K  [C_0402]  137.57 108.23 270 bottom
PCW16  1000P_0402_50V7K  [C_0402]  134.78 108.27 270 bottom
PCW17  82P_0402_50V8J  [C_0402]  136.66 108.22 270 bottom
PCZ01  8200P_0402_25V7K  [C_0402]  180.44 55.85 0 top
PCZ02  2200P_0402_50V7K  [C_0402]  182.25 55.33 0 bottom
PCZ03  15P_0402_50V8J  [C_0402]  180.44 56.73 0 top
PCZ04  1000P_0402_50V7K  [C_0402]  181.21 53.61 180 bottom
PCZ05  1000P_0402_50V7K  [C_0402]  179.02 56.24 180 top
PCZ06  1000P_0402_50V7K  [C_0402]  182.08 53.55 90 bottom
PCZ07  2200P_0402_25V7K  [C_0402]  181.41 55.39 180 bottom
PCZ08  0.01U_0402_25V7K  [C_0402]  180.51 56.39 90 bottom
PCZ09  1200P_0402_50V7K  [C_0402]  181.4 56.39 90 bottom
PCZ10  1000P_0402_50V7K  [C_0402]  180.41 51.72 270 bottom
PCZ11  3300P_0402_25V7K  [C_0402]  181.27 51.5 90 top
PCZ12  470P_0402_50V7K  [C_0402]  179.02 58.02 180 top
PCZ13  470P_0402_50V7K  [C_0402]  178.68 48.64 90 bottom
PCZ14  470P_0402_50V7K  [C_0402]  176.58 52.29 90 top
PCZ15  15P_0402_50V8J  [C_0402]  178.42 51.07 180 top
PCZ16  2200P_0402_50V7K  [C_0402]  177.52 49.28 90 top
PCZ17  820P_0402_50V7K  [C_0402]  176.29 50.46 180 bottom
PCZ18  1000P_0402_50V7K  [C_0402]  176.29 49.57 180 bottom
PCZ19  0.1U_0402_25V6  [C_0402]  174.64 52.32 90 top
PCZ20  0.1U_0402_25V6  [C_0402]  173.69 50.46 180 top
PCZ21  0.1U_0402_25V6  [C_0402]  174.39 50.46 180 bottom
PCZ22  1000P_0402_50V7K  [C_0402]  173.69 52.32 90 top
PCZ23  0.01U_0402_50V7K  [C_0402]  172.47 50.54 270 bottom
PCZ24  0.1U_0402_25V6  [C_0402]  179.01 61.12 90 top
PCZ25  470P_0402_50V7K  [C_0402]  175.63 59.47 270 top
PCZ26  0.022U_0402_16V7K  [C_0402]  174.56 61.9 180 top
PCZ27  5600P_0402_25V7K  [C_0402]  174.35 61.24 180 bottom
PCZ28  3300P_0402_50V7-K  [C_0402]  170.16 58.93 90 bottom
PCZ29  1000P_0402_50V7K  [C_0402]  171.53 60.68 180 top
PCZ30  15P_0402_50V8J  [C_0402]  172.61 61.24 180 bottom
PCZ31  2200P_0402_50V7K  [C_0402]  172.65 62.12 90 bottom
PCZ32  1000P_0402_50V7K  [C_0402]  174.73 59.47 270 top
PCZ33  2200P_0402_50V7K  [C_0402]  173.47 62.92 90 top
PCZ34  1U_0603_10V6K  [C_0603]  170.22 53.04 180 bottom
PCZ35  1000P_0402_50V7K  [C_0402]  168.96 59.03 0 top
PCZ36  1000P_0402_50V7K  [C_0402]  170.17 57.99 180 bottom
PD1  -  [TVNST52302AB0_SOT523-3]  54.07 118.36 90 top
PD2  -  [BAV99W_SC70-3]  61.5 120.81 0 top
PD3  -  [BAV99W_SC70-3]  61.5 116.1 180 top
PD4  S SCH DIO 5A 100V 15UA 0.88V TO227-3  [PDS5100H-13_POWERDI5-3]  96.51 140.89 180 top
PD5  -  [TVNST52302AB0_SOT523-3]  164.24 40.45 180 top
PD6  -  [TVNST52302AB0_SOT523-3]  167.89 42.55 0 top
PD10  -  [LRB715FT1G_SOT323-3]  93.95 150.96 90 top
PD11  -  [LRB715FT1G_SOT323-3]  82.63 138.26 0 top
PD12  -  [DFLS160-7_POWERDI123-2]  84.46 146.06 0 top
PD501  -  [SDMK0340L-7-F_SOD323-2]  26.06 86.36 180 bottom
PDB01  -  [SDMK0340L-7-F_SOD323-2]  204.16 54.34 0 bottom
PDB02  -  [SDMK0340L-7-F_SOD323-2]  204.15 56.11 0 bottom
PDB03  -  [SDMK0340L-7-F_SOD323-2]  203.35 58.88 135 bottom
PDB04  -  [BAT54CW_SOT323-3]  166.99 36.23 270 top
PDB05  -  [SDMK0340L-7-F_SOD323-2]  169.4 36.66 270 top
PDS01  -  [BAT54CW_SOT323-3]  54.73 121 180 top
PDS02  S SCH DIO 5A 100V 15UA 0.88V TO227-3  [PDS5100H-13_POWERDI5-3]  65.1 134.23 180 top
PDS03  -  [LRB715FT1G_SOT323-3]  52.33 119.2 180 top
PDS04  -  [SDMK0340L-7-F_SOD323-2]  44.98 121.68 270 top
PDS05  -  [SDMK0340L-7-F_SOD323-2]  47.54 121.79 0 top
PDS06  -  [SDMK0340L-7-F_SOD323-2]  47.54 120.07 0 top
PHV01  470K_0402_5%_TSM0B474J4702RE  [R_0402]  88.5 120.78 0 bottom
PHV02  10K_0402_5%_ERTJ0ER103J  [R_0402]  94.2 119.85 135 bottom
PHZ01  100K_0402_1%_B25/50 4250K  [R_0402]  151.59 56.32 0 bottom
PHZ02  220K_0402_5%_B25/50 4700K  [R_0402]  153.35 88.13 270 bottom
PHZ03  100K_0402_1%_B25/50 4250K  [R_0402]  158.07 98.15 180 bottom
PHZ04  100K_0402_1%_B25/50 4250K  [R_0402]  170.68 49.64 0 bottom
PHZ05  100K_0402_1%_B25/50 4250K  [R_0402]  157.2 96.67 0 bottom
PJP1  JUMP_43X79  [JUMP_43X79-NPM]  88.44 143.63 90 top
PJP2  -  [JUMP_43X79]  74.03 144.76 90 top
PJP3  JUMP_43X79  [JUMP_43X79-NPM]  148.68 36.14 90 bottom
PJP301  -  [JUMP_43X39]  20.46 37.73 90 bottom
PJP302  -  [JUMP_43X118]  28.49 56.35 0 bottom
PJP501  -  [JUMP_43X79]  28.04 102.84 270 bottom
PJP502  -  [JUMP_43X79]  27.21 109.11 90 top
PJP503  -  [JUMP_43X79]  27.21 109.14 90 bottom
PJP1801  -  [JUMP_43X39]  172.83 42.18 180 top
PJP1802  -  [JUMP_43X79]  155.76 44.22 180 bottom
PJP2501  -  [JUMP_43X39]  75.61 114.93 270 top
PJP2502  -  [JUMP_43X39]  60.85 112.2 180 top
PJPA01  -  [JUMP_43X39]  164.81 61.42 180 bottom
PJPB01  JUMP_43X118  [JUMP_43X118-NPM]  187.01 58.49 0 bottom
PJPDC1  ACES_50458-00601-001  [ACES_50458-00601-001_6P-T]  75.2 143.96 0 bottom
PJPG01  JUMP_43X79  [JUMP_43X79-NPM]  160.76 101.71 270 bottom
PJPH01  -  [JUMP_43X39]  166.58 55.48 180 top
PJPH02  -  [JUMP_43X118]  152.21 51.37 180 top
PJPI01  JUMP_43X79  [JUMP_43X79-NPM]  170.92 79.75 135 bottom
PJPM01  -  [JUMP_43X39]  51.05 25.12 90 top
PJPM02  -  [JUMP_43X118]  44.8 31.69 90 bottom
PJPM03  -  [JUMP_43X39]  40.12 33.92 90 top
PJPV01  JUMP_43X79  [JUMP_43X79-NPM]  88.65 140.25 180 bottom
PJPW01  -  [JUMP_43X39]  133.93 111.2 270 bottom
PJPW02  -  [JUMP_43X118]  157.52 111.65 90 bottom
PL1  5A Z150 20M 1210_2P  [5A_Z150_1210_2P]  88.44 142.83 90 top
PL2  5A Z150 20M 1210_2P  [5A_Z150_1210_2P-NPM]  74.03 143.96 90 top
PL3  BLM15AG102SN1D_2P  [MURAT_BLM15AG102SN1D_2P]  56.49 116.79 90 top
PL4  5A Z150 20M 1210_2P  [5A_Z150_1210_2P]  148.68 35.34 90 bottom
PL301  1.5UH_9A_20%_7X7X3_M  [L_7X7X3_M_2P]  26.1 43.87 90 bottom
PL311  5A_Z120_25M_0805_2P  [TAI-T_HCB2012KF-121T50_2P-NPM]  18.44 37.4 90 bottom
PL501  1.5UH_9A_20%_7X7X3_M  [L_7X7X3_M_2P]  19.34 98.82 90 bottom
PL511  5A Z150 20M 1210_2P  [5A_Z150_1210_2P-NPM]  28.04 103.64 270 bottom
PL1801  1UH_6.6A_20%_5X5X3_M  [L_5X5X3_M_2P]  164.35 44.37 180 bottom
PL1811  5A_Z120_25M_0805_2P  [TAI-T_HCB2012KF-121T50_2P]  174.23 42.88 180 bottom
PLA01  0.47UH 20% MMD-05CZ-R47MEV1L 12.2A  [L_5X5X3_M]  155.78 59.63 180 bottom
PLB01  1UH_PCMB104T-1R0MH_18A_20%  [CYNTE_PCMB104T-1R0MH_2P]  187.88 52.98 270 bottom
PLB11  5A Z150 20M 1210_2P  [5A_Z150_1210_2P]  186.21 58.49 0 bottom
PLG01  0.15UH 20% MMD-06DZER15MEM1L 36A  [L_7X7X4_M]  152.69 91.94 90 bottom
PLG11  5A Z150 20M 1210_2P  [5A_Z150_1210_2P]  160.76 102.51 270 bottom
PLH01  1UH_11A_20%_7X7X3_M  [L_7X7X3_M_2P]  158.09 51.57 180 bottom
PLH11  5A_Z120_25M_0805_2P  [TAI-T_HCB2012KF-121T50_2P-NPM]  167.29 56.31 180 bottom
PLI01  0.15UH 20% MMD-06DZER15MEM1L 36A  [L_7X7X4_M]  156.85 65.03 90 bottom
PLI02  0.15UH 20% MMD-06DZER15MEM1L 36A  [L_7X7X4_M]  157.61 87.84 270 bottom
PLI11  5A Z150 20M 1210_2P  [5A_Z150_1210_2P]  171.48 79.18 135 bottom
PLM01  1UH_11A_20%_7X7X3_M  [L_7X7X3_M_2P]  54.73 27.6 180 bottom
PLM11  5A_Z120_25M_0805_2P  [TAI-T_HCB2012KF-121T50_2P-NPM]  49.01 24.57 90 top
PLS11  5A_Z120_25M_0805_2P  [TAI-T_HCB2012KF-121T50_2P]  44.94 137.93 0 top
PLS12  5A_Z120_25M_0805_2P  [TAI-T_HCB2012KF-121T50_2P]  44.94 139.72 0 top
PLV01  0.22UH_24A_20%_7X7X4_MOLDING  [L_7X7X4_M]  97.21 122.95 135 bottom
PLV02  0.22UH_24A_20%_7X7X4_MOLDING  [L_7X7X4_M]  97.39 137.94 225 bottom
PLV11  5A Z150 20M 1210_2P  [5A_Z150_1210_2P]  89.44 140.21 180 bottom
PLW01  1UH_6.6A_20%_5X5X3_M  [L_5X5X3_M_2P]  147.39 110.16 0 bottom
PLW11  5A_Z120_25M_0805_2P  [TAI-T_HCB2012KF-121T50_2P-NPM]  136.09 111.75 270 bottom
PQ1  -  [FDV301N-G_SOT23-3]  57.95 118.35 0 top
PQ2  -  [MMST3904-7-F_SOT323-3]  59.53 115.88 90 top
PQ3  -  [AON7409_DFN8-5]  93.55 146.07 270 top
PQ4  -  [AON7409_DFN8-5]  101.13 144.17 90 top
PQ5  2N7002KW_SOT323-3  [DMN65D8LW-7_SOT323-3]  91.73 149.71 0 bottom
PQ6  2N7002KW_SOT323-3  [DMN65D8LW-7_SOT323-3]  93.86 146.16 180 bottom
PQ11  2N7002KW_SOT323-3  [DMN65D8LW-7_SOT323-3]  174.92 31.26 90 top
PQ12  2N7002KDW_SOT363-6  [DMN65D8LDW-7_SOT363-6]  172.13 29.25 90 top
PQ13  2N7002KDW_SOT363-6  [DMN65D8LDW-7_SOT363-6]  173.28 33.99 0 top
PQ15  2N7002KW_SOT323-3  [DMN65D8LW-7_SOT323-3]  93.88 148.51 270 bottom
PQ16  2N7002KW_SOT323-3  [DMN65D8LW-7_SOT323-3]  90.75 148.48 270 top
PQ17  2N7002KW_SOT323-3  [DMN65D8LW-7_SOT323-3]  90.03 147.34 180 bottom
PQ18  2N7002KW_SOT323-3  [DMN65D8LW-7_SOT323-3]  91.12 143.49 90 bottom
PQ19  -  [AO3409_SOT23-3]  101.28 146.77 270 bottom
PQ20  2N7002KW_SOT323-3  [DMN65D8LW-7_SOT323-3]  105.09 147.47 90 bottom
PQA01  TR PE642DT 2N PDFN3X3S  [AON7934_DFN3X3A8-10]  158.41 61.18 0 bottom
PQB01  -  [AON6994_DFN5X6D-8-7]  194.27 53.58 0 bottom
PQB02  -  [AON6994_DFN5X6D-8-7]  194.5 37.7 135 bottom
PQB03  -  [AON7409_DFN8-5]  149.98 30.46 180 bottom
PQB04  2N7002KW_SOT323-3  [DMN65D8LW-7_SOT323-3]  192.79 35.35 0 top
PQM01  TR PE642DT 2N PDFN3X3S  [AON7934_DFN3X3A8-10]  44.08 28.09 0 bottom
PQS01  -  [AON7409_DFN8-5]  51.43 139.16 270 top
PQS02  -  [AON7409_DFN8-5]  63.95 137.63 90 top
PQS03  2N7002KDW_SOT363-6  [DMN65D8LDW-7_SOT363-6]  56.47 130.87 0 top
PQS04  2N7002KW_SOT323-3  [DMN65D8LW-7_SOT323-3]  54.52 131.12 0 top
PQS05  2N7002KDW_SOT363-6  [DMN65D8LDW-7_SOT363-6]  58.2 129.68 270 top
PQS06  -  [AO3409_SOT23-3]  62.18 129.54 270 top
PQS07  2N7002KW_SOT323-3  [DMN65D8LW-7_SOT323-3]  65.31 126.11 270 top
PQS08  2N7002KW_SOT323-3  [DMN65D8LW-7_SOT323-3]  49.59 125.63 0 top
PQS10  2N7002KDW_SOT363-6  [DMN65D8LDW-7_SOT363-6]  63.37 121.4 0 top
PQS11  2N7002KW_SOT323-3  [DMN65D8LW-7_SOT323-3]  65.31 119.57 270 top
PQS12  2N7002KW_SOT323-3  [DMN65D8LW-7_SOT323-3]  50.65 129.22 90 top
PQS13  -  [AO3409_SOT23-3]  50.17 133.47 270 top
PQS14  2N7002KW_SOT323-3  [DMN65D8LW-7_SOT323-3]  69 135.44 0 top
PQS30  2N7002KDW_SOT363-6  [DMN65D8LDW-7_SOT363-6]  45.26 123.64 90 top
PQV01  -  [AON6994_DFN5X6D-8-7]  85.17 122.38 0 top
PQV02  -  [AON6994_DFN5X6D-8-7]  88.98 122.38 180 bottom
PQV03  -  [AON6994_DFN5X6D-8-7]  89.03 137.5 180 top
PQV04  -  [AON6994_DFN5X6D-8-7]  85.22 137.5 0 bottom
PR1  33_0402_5%  [R_0402]  56.97 122.11 0 top
PR2  0_0402_5%  [R_0402]  90.04 150.1 90 bottom
PR3  100K_0402_1%  [R_0402]  55.61 116.9 180 top
PR4  10K_0402_1%  [R_0402]  59.85 117.71 270 top
PR5  2.2K_0402_5%  [R_0402]  58.62 122.11 0 top
PR6  15K_0402_1%  [R_0402]  54.69 116.07 0 top
PR7  100K_0402_1%  [R_0402]  60.68 114.92 90 top
PR8  1M_0402_5%  [R_0402]  90.88 144.58 270 top
PR9  1M_0402_5%  [R_0402]  101.53 148.6 180 top
PR10  1M_0402_5%  [R_0402]  92.81 148.42 90 bottom
PR11  510K_0402_5%  [R_0402]  96.55 145.26 180 bottom
PR12  1M_0402_5%  [R_0402]  96.57 146.06 180 bottom
PR13  100K_0402_5%  [R_0402]  93.29 152.84 180 top
PR14  10K_0402_5%  [R_0402]  89.95 150.54 0 top
PR15  12K_0402_1%  [R_0402]  91.36 152.59 180 top
PR16  100K_0402_5%  [R_0402]  90.88 151.34 180 top
PR17  56K_0402_5%  [R_0402]  95.65 143.52 0 bottom
PR21  100K_0402_5%  [R_0402]  92.08 148.32 90 top
PR22  100K_0402_5%  [R_0402]  87.79 149.23 270 top
PR31  0_0402_5%  [R_0402]  174.12 32.18 90 top
PR32  3.3K_1206_5%  [R_1206]  171.32 36.87 270 top
PR33  10K_0402_1%  [R_0402]  171.26 28 180 top
PR34  1M_0402_1%  [R_0402]  172.67 37.85 0 top
PR35  0_0402_5%  [R_0402]  175.92 33.09 180 top
PR36  1M_0402_1%  [R_0402]  171.28 33.05 270 top
PR37  100_0402_5%  [R_0402]  165.67 41.03 90 top
PR38  1M_0402_1%  [R_0402]  173.79 36.93 0 top
PR39  200_0402_5%  [R_0402]  165.63 40.27 0 top
PR40  100K_0402_1%  [R_0402]  169.15 30.76 90 top
PR41  10K_0402_1%  [R_0402]  166.47 41.03 90 top
PR42  100_0402_5%  [R_0402]  161.68 42.05 0 top
PR43  100K_0402_1%  [R_0402]  177.02 29.54 180 top
PR44  1M_0402_1%  [R_0402]  173.03 29.2 90 top
PR45  1M_0402_1%  [R_0402]  173.34 33.05 180 top
PR46  0_0402_5%  [R_0402]  92.85 148.32 90 top
PR47  300K_0402_5%  [R_0402]  91.97 147.71 90 bottom
PR48  100K_0402_5%  [R_0402]  90.78 149.28 270 bottom
PR49  0_0402_5%  [R_0402]  87.22 143.59 270 bottom
PR50  100K_0402_5%  [R_0402]  91.86 146.88 270 bottom
PR51  0_0402_5%  [R_0402]  94.42 143.02 180 bottom
PR52  0_0402_5%  [R_0402]  52.07 120.29 90 top
PR60  100K_0402_5%  [R_0402]  92.2 142.58 90 bottom
PR61  100K_0402_5%  [R_0402]  47.41 125.79 180 top
PR62  15K_0402_5%  [R_0402]  45.4 125.99 180 top
PR63  100K_0402_5%  [R_0402]  43.38 126 180 top
PR64  100K_0402_5%  [R_0402]  47.85 123.49 90 top
PR65  0_0402_5%  [R_0402]  46.15 124.29 0 top
PR66  1M_0402_1%  [R_0402]  47.06 123.46 180 top
PR100  1M_0402_5%  [R_0402]  92.81 152.64 0 bottom
PR301  0_0603_5%  [R0603_0OHM]  20.98 39.99 0 bottom
PR302  499K_0402_1%  [R_0402]  18.16 46.09 90 bottom
PR303  150K_0402_1%  [R_0402]  19.01 46.07 90 bottom
PR304  10K_0402_1%  [R_0402]  19.43 44.52 180 top
PR305  4.7_1206_5%  [R_1206]  26.62 43.85 180 top
PR306  1K_0402_5%  [R_0402]  21.52 47.86 180 bottom
PR307  150K_0402_1%  [R_0402]  20.61 46.99 270 bottom
PR308  150K_0402_1%  [R_0402]  19.83 46.08 90 bottom
PR501  0_0603_5%  [R0603_0OHM]  23.76 100.15 90 bottom
PR502  0_0402_5%  [R0402_0OHM]  21.41 86 0 bottom
PR503  0_0402_5%  [R0402_0OHM]  26.74 94.08 270 bottom
PR504  10K_0402_1%  [R_0402]  27.66 92.57 90 bottom
PR505  4.7_1206_5%  [R_1206]  20.75 99.48 90 top
PR506  2.2K_0402_5%  [R_0402]  21.41 86.77 0 bottom
PR507  0_0402_5%  [R0402_0OHM]  27.12 83.36 90 bottom
PR508  1M_0402_5%  [R_0402]  26.86 91.5 180 bottom
PR509  1K_0402_5%  [R_0402]  24.23 92.31 90 bottom
PR510  150K_0402_1%  [R_0402]  24.21 94.04 0 bottom
PR511  150K_0402_1%  [R_0402]  25.94 94.06 270 bottom
PR1801  0_0402_5%  [R_0402]  165.83 47.8 270 bottom
PR1802  1M_0402_5%  [R_0402]  167.64 47.42 0 bottom
PR1803  100K_0402_5%  [R_0402]  166.92 45.97 270 top
PR1804  4.7_1206_5%  [R_1206]  164.63 46.16 270 top
PR1805  10K_0402_1%  [R_0402]  169.39 46.53 90 bottom
PR1806  0_0402_5%  [R_0402]  166.84 46.46 90 bottom
PR1807  20K_0402_1%  [R_0402]  171.04 47.44 270 bottom
PR1890  0_0402_5%  [R_0402]  164.12 47.77 0 bottom
PR2501  0_0402_5%  [R0402_0OHM]  73.11 112.28 0 top
PR2502  21.5K_0402_1%  [R_0402]  63.85 112.42 270 top
PR2503  10K_0402_1%  [R_0402]  65.62 109.15 0 top
PR2504  2.2_0402_1%  [R_0402]  71.41 116.34 270 top
PRA01  2.2_0603_5%  [R_0603]  165.16 60.88 180 top
PRA02  4.7_1206_5%  [R_1206]  155.75 61.51 270 top
PRB01  0.02_1206_1%  [R_1206_4P-D]  184.17 60.39 270 bottom
PRB02  2.2_0402_1%  [R_0402]  199.27 48.03 0 bottom
PRB03  2.2_0402_1%  [R_0402]  199.25 47.15 0 bottom
PRB04  0_0603_5%  [R_0603]  199.42 49.13 0 bottom
PRB05  442K_0402_1%  [R_0402]  199.67 50.14 0 bottom
PRB06  3.3_0603_1%  [R_0603]  200.82 46.14 180 bottom
PRB07  100K_0402_5%  [R_0402]  200.45 51.75 180 top
PRB08  1_0805_5%~D  [R_0805]  202.34 51.82 270 bottom
PRB09  4.7_0402_5%  [R_0402]  202.62 44.7 180 top
PRB10  0_0402_5%  [R0402_0OHM]  204.73 48.6 270 top
PRB11  100K_0402_1%  [R_0402]  207.06 52.47 270 bottom
PRB12  0.01_1206_1%  [R_1206_4P-D]  182 42.76 180 bottom
PRB13  0_0402_5%  [R_0402]  203.83 49.91 90 bottom
PRB14  0_0402_5%  [R0402_0OHM]  204.62 50.82 270 bottom
PRB15  4.7_0603_1%  [R_0603]  202.02 39.77 90 bottom
PRB16  0_0402_5%  [R0402_0OHM]  205.46 50.82 270 bottom
PRB17  4.7_1206_5%  [R_1206]  188.91 54.17 270 top
PRB18  4.7_1206_5%  [R_1206]  191.82 44.39 180 top
PRB19  0_0402_5%  [R_0402]  206.27 50.81 270 bottom
PRB20  154K_0402_1%  [R_0402]  192.73 36.52 0 top
PRB21  0_0402_5%  [R0402_0OHM]  204.31 41.27 270 bottom
PRB22  0_0402_5%  [R0402_0OHM]  207.06 49.9 90 bottom
PRB23  1M_0402_1%  [R_0402]  191.93 32.44 270 top
PRB24  100K_0402_1%  [R_0402]  206.74 46.27 180 top
PRB25  100K_0402_1%  [R_0402]  206.62 47.09 90 top
PRB26  105K_0402_1%  [R_0402]  208.73 45.59 0 top
PRB27  100K_0402_1%  [R_0402]  209.65 47.18 180 top
PRB28  0_0402_5%  [R0402_0OHM]  208.24 45.19 0 bottom
PRB29  0_0402_5%  [R0402_0OHM]  209.65 46.36 180 top
PRB30  499_0402_1%  [R_0402]  208.2 47.06 0 bottom
PRB31  0_0402_5%  [R0402_0OHM]  208.05 44.36 0 bottom
PRB32  1_0402_1%  [R_0402]  205.22 40.37 270 bottom
PRB33  10.5K_0402_1%  [R_0402]  208.24 43.65 0 top
PRB34  0_0402_5%  [R0402_0OHM]  209.88 44.41 0 bottom
PRB35  0_0402_5%  [R0402_0OHM]  209.88 45.19 0 bottom
PRB36  1_0402_1%  [R_0402]  206.14 40.37 270 bottom
PRB37  0_0402_5%  [R_0402]  168.04 36.48 270 top
PRB38  0_0402_5%  [R_0402]  164.04 35.31 90 top
PRB39  100_0402_5%  [R_0402]  208.96 43.54 180 bottom
PRB40  0_0402_5%  [R_0402]  164.04 36.95 90 top
PRB41  0_0402_5%  [R_0402]  164.04 34.36 270 top
PRB42  0_0402_5%  [R_0402]  167.75 31.86 270 top
PRB43  100K_0402_1%  [R_0402]  192.81 32.38 0 top
PRB44  0_0402_5%  [R_0402]  168.82 32.8 0 top
PRC01  0.0002_0805_5%  [R_0805]  122.79 73.73 90 top
PRC02  0.0002_0805_5%  [R_0805]  129.94 79.76 270 top
PRC03  0.0002_0805_5%  [R_0805]  129.11 74.08 0 top
PRC04  SOLDER_0603  [SOLDER_PREFORMS_0603-NPM]  122.77 73.86 90 top
PRC05  SOLDER_0603  [SOLDER_PREFORMS_0603-NPM]  129.93 79.6 270 top
PRC06  SOLDER_0603  [SOLDER_PREFORMS_0603-NPM]  129.26 74.13 0 top
PRG01  3.9_0603_1%  [R_0603]  160.09 96.5 90 bottom
PRG02  2_0402_1%  [R_0402]  157.79 95.16 0 top
PRG03  4.7_1206_5%  [R_1206]  152.12 91.62 0 top
PRH01  0_0402_5%  [R_0402]  165.83 53.43 180 bottom
PRH02  1M_0402_1%  [R_0402]  164.93 52.76 0 top
PRH03  0_0402_5%  [R0402_0OHM]  165.85 49.28 180 bottom
PRH04  0_0402_5%  [R_0402]  164.87 49.46 0 top
PRH05  100K_0402_5%  [R_0402]  165.83 52.65 180 bottom
PRH06  10_0603_5%  [R_0603]  163.47 50.41 180 top
PRH07  4.7_1206_5%  [R_1206]  158.42 53 270 top
PRH08  21.5K_0402_1%  [R_0402]  164.93 51.11 0 top
PRH09  31.6K_0402_1%  [R_0402]  164.93 50.9 0 bottom
PRH11  2.2_0402_1%  [R_0402]  165.85 50.07 180 bottom
PRH12  1K_0402_1%  [R_0402]  165.81 51.93 180 top
PRH13  0_0402_5%  [R_0402]  165.83 54.21 180 bottom
PRH90  0_0402_5%  [R_0402]  165.83 55 180 bottom
PRI01  3.9_0603_1%  [R_0603]  164.47 70.23 90 top
PRI02  2_0402_1%  [R_0402]  161.36 69.11 90 top
PRI03  4.7_1206_5%  [R_1206]  156.9 64.82 0 top
PRI21  3.9_0603_1%  [R_0603]  166.79 84.51 270 top
PRI22  2_0402_1%  [R_0402]  168.23 88.22 0 bottom
PRI23  4.7_1206_5%  [R_1206]  157.58 87.98 0 top
PRM01  4.7_1206_5%  [R_1206]  49.04 29.4 0 top
PRM02  2.2_0603_5%  [R_0603]  39.85 30.34 0 top
PRM03  15.4K_0402_1%  [R_0402]  37.75 24.72 270 top
PRM04  5.1_0603_5%  [R_0603]  34.22 23.91 90 top
PRM05  2.2_0603_5%  [R_0603]  35.49 25.3 270 top
PRM06  10K_0402_1%  [R_0402]  32.72 26.66 0 top
PRM07  453K_0402_1%  [R_0402]  32.8 27.47 0 top
PRM08  0_0402_5%  [R0402_0OHM]  32.8 28.28 0 top
PRM09  0_0402_5%  [R0402_0OHM]  32.73 30.92 0 top
PRM10  60.4K_0402_1%  [R_0402]  34.04 33.13 0 top
PRM11  100K_0402_1%  [R_0402]  33.18 32.2 90 top
PRS01  1.8M_0402_1%  [R_0402]  49.07 117.11 180 top
PRS02  1K_0402_1%  [R_0402]  46.47 118.73 0 top
PRS03  240K_0402_1%  [R_0402]  51.53 112.86 270 top
PRS04  102K_0402_1%  [R_0402]  46.47 117.86 0 top
PRS05  23.2K_0402_1%  [R_0402]  49.95 117.1 90 top
PRS06  84.5K_0402_1%  [R_0402]  47.38 117.1 180 top
PRS07  100K_0402_5%  [R_0402]  48.04 136.6 270 top
PRS08  499K_0402_1%  [R_0402]  48.87 136.6 270 top
PRS09  499K_0402_1%  [R_0402]  66.2 138.54 90 top
PRS10  300K_0402_1%  [R_0402]  65.95 130.56 270 top
PRS11  49.9K_0402_1%  [R_0402]  51.14 135.95 0 top
PRS12  10K_0402_5%  [R_0402]  48.59 126.72 0 top
PRS13  100K_0402_5%  [R_0402]  56.19 133.74 0 top
PRS14  100K_0402_5%  [R_0402]  58.82 130.93 0 top
PRS15  100K_0402_5%  [R_0402]  65.95 128.85 270 top
PRS16  49.9K_0402_1%  [R_0402]  61.45 130.93 180 top
PRS18  0_0402_5%  [R_0402]  61.36 126.23 270 top
